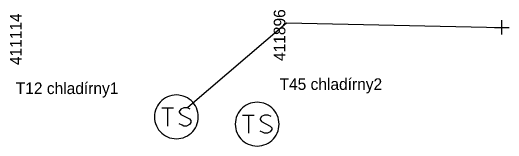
# Model space of a CAD drawing. Extents: x -540247 to -537390, y -1183887 to -1180355.
# Drawn here: x -540174.12 to -540131.11, y -1183425.24 to -1183413.49 of the extents above; entities that cross this region are included whole.
import ezdxf

# ---------------------------------------------------------------- set-up
doc = ezdxf.new("R2010")
doc.units = 0
for name, color, linetype in [('Vrstva 1', 7, 'Continuous'), ('Vrstva 25', 7, 'Continuous'), ('Vrstva 26', 7, 'Continuous'), ('Vrstva 27', 7, 'Continuous'), ('Vrstva 34', 7, 'Continuous'), ('Vrstva 59', 7, 'Continuous'), ('Vrstva 6', 7, 'Continuous')]:
    doc.layers.add(name, color=color, linetype=linetype)

# ---------------------------------------------------------------- blocks, each defined once
blk = doc.blocks.new('NN800')
at = {"layer": 'Vrstva 1'}
for points in [[(-0.442, 0.442), (0.442, -0.442)], [(-0.442, -0.442), (0.442, 0.442)]]:
    blk.add_lwpolyline(points, dxfattribs=at)
blk = doc.blocks.new('NN610')
at = {"layer": 'Vrstva 6'}
for points in [[(1.883, -0.001), (1.872, 0.196), (1.841, 0.392), (1.79, 0.583), (1.718, 0.768), (1.629, 0.943), (1.521, 1.109), (1.397, 1.263), (1.257, 1.403), (1.103, 1.527), (0.937, 1.635), (0.761, 1.725), (0.577, 1.796), (0.19, 1.878), (0.19, 1.878), (-0.007, 1.889), (-0.205, 1.878), (-0.401, 1.847), (-0.591, 1.796), (-0.777, 1.725), (-0.952, 1.635), (-1.118, 1.527), (-1.272, 1.403), (-1.412, 1.263), (-1.536, 1.109), (-1.644, 0.943), (-1.734, 0.768), (-1.805, 0.583), (-1.856, 0.392), (-1.887, 0.196), (-1.898, -0.001), (-1.887, -0.199), (-1.856, -0.395), (-1.805, -0.585), (-1.734, -0.77), (-1.644, -0.946), (-1.536, -1.112), (-1.411, -1.266), (-1.272, -1.405), (-1.118, -1.53), (-0.952, -1.638), (-0.776, -1.728), (-0.591, -1.799), (-0.401, -1.85), (-0.205, -1.881), (-0.007, -1.892), (0.19, -1.881), (0.385, -1.85), (0.577, -1.799), (0.761, -1.728), (0.937, -1.638), (1.103, -1.53), (1.257, -1.405), (1.397, -1.266), (1.521, -1.112), (1.629, -0.946), (1.718, -0.77), (1.79, -0.585), (1.841, -0.395), (1.872, -0.199), (1.883, -0.001)], [(-1.269, 0.782), (-0.261, 0.782)], [(-0.765, 0.782), (-0.765, -0.792)], [(1.188, 0.656), (0.936, 0.782), (0.621, 0.782), (0.369, 0.656), (0.243, 0.468), (0.243, 0.404), (0.369, 0.216), (1.125, -0.162), (1.251, -0.32), (1.251, -0.478), (1.125, -0.666), (0.873, -0.792), (0.621, -0.792), (0.495, -0.73), (0.243, -0.604)]]:
    blk.add_lwpolyline(points, dxfattribs=at)

msp = doc.modelspace()

# ---------------------------------------------------------------- linework, layer by layer
at = {"layer": 'Vrstva 59'}
msp.add_lwpolyline([(-540158.809, -1183421.892), (-540150.3, -1183414.6), (-540131.738, -1183414.988)], dxfattribs=at)

# ---------------------------------------------------------------- block references
at = {"layer": 'Vrstva 25'}
for p in [(-540159.773, -1183422.718), (-540152.81, -1183423.344)]:
    msp.add_blockref('NN610', p, dxfattribs=at)
at = {"layer": 'Vrstva 34', "rotation": 45}
msp.add_blockref('NN800', (-540131.738, -1183414.988), dxfattribs=at)

# ---------------------------------------------------------------- texts
at = {"layer": 'Vrstva 26'}
for s, p in [('411114', (-540173.123, -1183418.248)), ('411896', (-540150.391, -1183417.891))]:
    msp.add_text(s, height=1, rotation=90, dxfattribs=at).set_placement(p)
at = {"layer": 'Vrstva 27'}
for s, p in [('T45 chladírny2', (-540150.891, -1183420.391)), ('T12 chladírny1', (-540173.623, -1183420.748))]:
    msp.add_text(s, height=1, dxfattribs=at).set_placement(p)

doc.saveas('drawing.dxf')
